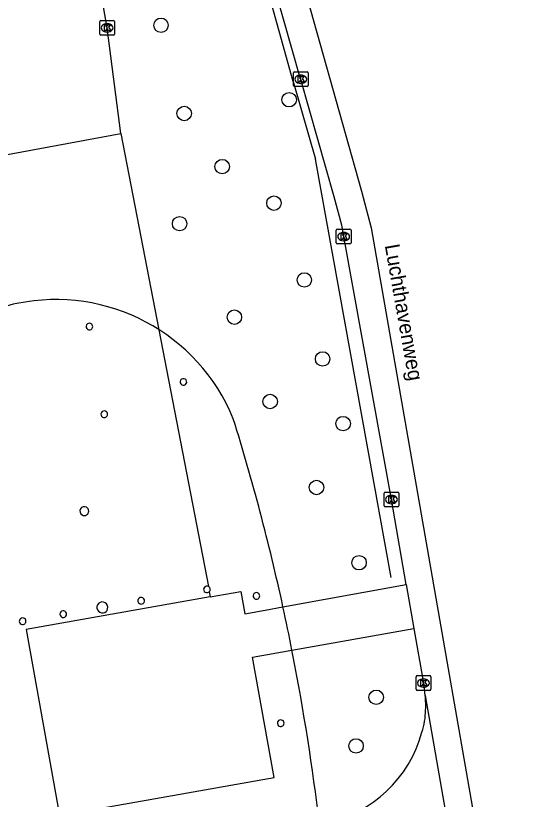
# Model space of a CAD drawing. Extents: x 152881 to 155736, y 382924 to 386919.
# Drawn here: x 155377.3 to 155412.3, y 385358.1 to 385411.1 of the extents above; entities that cross this region are included whole.
import ezdxf

# ---------------------------------------------------------------- set-up
doc = ezdxf.new("R2010")
doc.units = 0
for name, color, linetype in [('IMGEO_Boom', 7, 'Continuous'), ('IMGEO_Hek', 7, 'Continuous'), ('IMGEO_Kolk', 7, 'Continuous'), ('IMGEO_Openbare_ruimte_label', 7, 'Continuous'), ('IMGEO_Pand', 7, 'Continuous'), ('IMGEO_Pand_overbouw', 7, 'Continuous'), ('IMGEO_Rijbaan_lokaal_gesloten', 7, 'Continuous'), ('IMGEO_Voetpad_open', 7, 'Continuous')]:
    doc.layers.add(name, color=color, linetype=linetype)

msp = doc.modelspace()

# ---------------------------------------------------------------- linework, layer by layer
at = {"layer": 'IMGEO_Boom'}
for centre in [(155387.178, 385410.464), (155395.846, 385405.423), (155388.747, 385404.497), (155391.319, 385400.896), (155394.817, 385398.427), (155388.438, 385397.038), (155396.875, 385393.231), (155392.142, 385390.711), (155398.109, 385387.882), (155394.56, 385385.001), (155399.498, 385383.509), (155397.698, 385379.188), (155400.578, 385374.096), (155401.736, 385364.991), (155400.373, 385361.698)]:
    msp.add_circle(centre, 0.489, dxfattribs=at)
at = {"layer": 'IMGEO_Hek'}
for points in [[(155396.115, 385406.669), (155391.617, 385422.907)], [(155396.115, 385406.669), (155397.634, 385401.404)], [(155402.753, 385373.089), (155397.634, 385401.404)]]:
    msp.add_lwpolyline(points, dxfattribs=at)
at = {"layer": 'IMGEO_Kolk'}
for p, q in [((155383.03, 385409.86), (155383.03, 385410.712)), ((155383.105, 385410.786), (155383.957, 385410.786)), ((155384.031, 385410.712), (155384.031, 385409.86)), ((155383.518, 385410.566), (155383.543, 385410.566)), ((155383.957, 385409.786), (155383.105, 385409.786)), ((155383.541, 385410.006), (155383.516, 385410.006)), ((155396.131, 385406.385), (155396.131, 385407.237)), ((155396.206, 385407.311), (155397.058, 385407.311)), ((155396.619, 385407.091), (155396.644, 385407.091)), ((155397.132, 385407.237), (155397.132, 385406.385)), ((155396.642, 385406.531), (155396.617, 385406.531)), ((155397.058, 385406.311), (155396.206, 385406.311)), ((155399.036, 385395.737), (155399.036, 385396.589)), ((155399.111, 385396.663), (155399.963, 385396.663)), ((155399.524, 385396.443), (155399.549, 385396.443)), ((155400.037, 385396.589), (155400.037, 385395.737)), ((155399.547, 385395.883), (155399.522, 385395.883)), ((155399.963, 385395.663), (155399.111, 385395.663)), ((155402.342, 385378.869), (155403.194, 385378.869)), ((155402.267, 385377.943), (155402.267, 385378.795)), ((155402.755, 385378.649), (155402.78, 385378.649)), ((155403.268, 385378.795), (155403.268, 385377.943)), ((155403.194, 385377.869), (155402.342, 385377.869)), ((155402.778, 385378.089), (155402.753, 385378.089)), ((155404.432, 385365.529), (155404.432, 385366.381)), ((155404.507, 385366.455), (155405.359, 385366.455)), ((155404.92, 385366.235), (155404.945, 385366.235)), ((155405.433, 385366.381), (155405.433, 385365.529)), ((155404.943, 385365.675), (155404.918, 385365.675)), ((155405.359, 385365.455), (155404.507, 385365.455))]:
    msp.add_line(p, q, dxfattribs=at)
for points in [[(155383.03, 385409.86), (155383.03, 385410.712)], [(155383.105, 385410.786), (155383.957, 385410.786)], [(155384.031, 385410.712), (155384.031, 385409.86)], [(155383.351, 385410.486), (155383.474, 385410.486), (155383.474, 385410.335), (155383.604, 385410.486), (155383.768, 385410.486), (155383.622, 385410.335), (155383.775, 385410.086), (155383.623, 385410.086), (155383.538, 385410.25), (155383.474, 385410.183), (155383.474, 385410.086), (155383.351, 385410.086), (155383.351, 385410.486)], [(155383.957, 385409.786), (155383.105, 385409.786)], [(155396.131, 385406.385), (155396.131, 385407.237)], [(155396.206, 385407.311), (155397.058, 385407.311)], [(155396.452, 385407.011), (155396.575, 385407.011), (155396.575, 385406.86), (155396.705, 385407.011), (155396.869, 385407.011), (155396.723, 385406.86), (155396.876, 385406.611), (155396.724, 385406.611), (155396.639, 385406.775), (155396.575, 385406.708), (155396.575, 385406.611), (155396.452, 385406.611), (155396.452, 385407.011)], [(155397.132, 385407.237), (155397.132, 385406.385)], [(155397.058, 385406.311), (155396.206, 385406.311)], [(155399.036, 385395.737), (155399.036, 385396.589)], [(155399.111, 385396.663), (155399.963, 385396.663)], [(155400.037, 385396.589), (155400.037, 385395.737)], [(155399.357, 385396.363), (155399.48, 385396.363), (155399.48, 385396.212), (155399.61, 385396.363), (155399.774, 385396.363), (155399.628, 385396.212), (155399.781, 385395.963), (155399.629, 385395.963), (155399.544, 385396.127), (155399.48, 385396.06), (155399.48, 385395.963), (155399.357, 385395.963), (155399.357, 385396.363)], [(155399.963, 385395.663), (155399.111, 385395.663)], [(155402.342, 385378.869), (155403.194, 385378.869)], [(155402.267, 385377.943), (155402.267, 385378.795)], [(155402.588, 385378.569), (155402.711, 385378.569), (155402.711, 385378.418), (155402.841, 385378.569), (155403.005, 385378.569), (155402.859, 385378.418), (155403.012, 385378.169), (155402.86, 385378.169), (155402.775, 385378.333), (155402.711, 385378.266), (155402.711, 385378.169), (155402.588, 385378.169), (155402.588, 385378.569)], [(155403.268, 385378.795), (155403.268, 385377.943)], [(155403.194, 385377.869), (155402.342, 385377.869)], [(155404.432, 385365.529), (155404.432, 385366.381)], [(155404.507, 385366.455), (155405.359, 385366.455)], [(155404.753, 385366.155), (155404.876, 385366.155), (155404.876, 385366.004), (155405.006, 385366.155), (155405.17, 385366.155), (155405.024, 385366.004), (155405.177, 385365.755), (155405.025, 385365.755), (155404.94, 385365.919), (155404.876, 385365.852), (155404.876, 385365.755), (155404.753, 385365.755), (155404.753, 385366.155)], [(155405.433, 385366.381), (155405.433, 385365.529)], [(155405.359, 385365.455), (155404.507, 385365.455)]]:
    msp.add_lwpolyline(points, dxfattribs=at)
for centre, start, end in [((155383.107, 385410.71), 91.552, 178.448), ((155383.107, 385410.71), 91.552, 178.448), ((155383.955, 385410.71), 1.552, 88.448), ((155383.955, 385410.71), 1.552, 88.448), ((155383.107, 385409.862), 181.552, 268.448), ((155383.107, 385409.862), 181.552, 268.448), ((155383.955, 385409.862), 271.552, 358.448), ((155383.955, 385409.862), 271.552, 358.448), ((155396.208, 385407.235), 91.552, 178.448), ((155396.208, 385407.235), 91.552, 178.448), ((155397.056, 385407.235), 1.552, 88.448), ((155397.056, 385407.235), 1.552, 88.448), ((155396.208, 385406.387), 181.552, 268.448), ((155396.208, 385406.387), 181.552, 268.448), ((155397.056, 385406.387), 271.552, 358.448), ((155397.056, 385406.387), 271.552, 358.448), ((155399.113, 385396.587), 91.552, 178.448), ((155399.113, 385396.587), 91.552, 178.448), ((155399.961, 385396.587), 1.552, 88.448), ((155399.961, 385396.587), 1.552, 88.448), ((155399.113, 385395.739), 181.552, 268.448), ((155399.113, 385395.739), 181.552, 268.448), ((155399.961, 385395.739), 271.552, 358.448), ((155399.961, 385395.739), 271.552, 358.448), ((155402.344, 385378.793), 91.552, 178.448), ((155402.344, 385378.793), 91.552, 178.448), ((155403.192, 385378.793), 1.552, 88.448), ((155403.192, 385378.793), 1.552, 88.448), ((155402.344, 385377.945), 181.552, 268.448), ((155402.344, 385377.945), 181.552, 268.448), ((155403.192, 385377.945), 271.552, 358.448), ((155403.192, 385377.945), 271.552, 358.448), ((155404.509, 385366.379), 91.552, 178.448), ((155404.509, 385366.379), 91.552, 178.448), ((155405.357, 385366.379), 1.552, 88.448), ((155405.357, 385366.379), 1.552, 88.448), ((155404.509, 385365.531), 181.552, 268.448), ((155404.509, 385365.531), 181.552, 268.448), ((155405.357, 385365.531), 271.552, 358.448), ((155405.357, 385365.531), 271.552, 358.448)]:
    msp.add_arc(centre, 0.0765, start, end, dxfattribs=at)
for centre, major_axis, ratio, start_param, end_param in [((155383.517, 385410.286), (-0.387, 0.002), 0.722429, 4.712389, 7.853982), ((155383.542, 385410.286), (-0.39, 0.002), 0.717154, 1.570796, 4.712389), ((155396.618, 385406.811), (-0.387, 0.002), 0.722429, 4.712389, 7.853982), ((155396.643, 385406.811), (-0.39, 0.002), 0.717154, 1.570796, 4.712389), ((155399.523, 385396.163), (-0.387, 0.002), 0.722429, 4.712389, 7.853982), ((155399.548, 385396.163), (-0.39, 0.002), 0.717154, 1.570796, 4.712389), ((155402.754, 385378.369), (-0.387, 0.002), 0.722429, 4.712389, 7.853982), ((155402.779, 385378.369), (-0.39, 0.002), 0.717154, 1.570796, 4.712389), ((155404.919, 385365.955), (-0.387, 0.002), 0.722429, 4.712389, 7.853982), ((155404.944, 385365.955), (-0.39, 0.002), 0.717154, 1.570796, 4.712389)]:
    msp.add_ellipse(centre, major_axis=major_axis, ratio=ratio, start_param=start_param, end_param=end_param, dxfattribs=at)
at = {"layer": 'IMGEO_Pand'}
for centre, radius, start, end in [((155382.336, 385390.073), 0.225, 60.273, 239.7637), ((155382.336, 385390.073), 0.225, 239.9083, 60.1285), ((155388.693, 385386.326), 0.225, 60.0184, 240.0184), ((155388.693, 385386.326), 0.225, 240.2022, 59.8345), ((155383.34, 385384.14), 0.225, 60.0184, 240.0184), ((155383.341, 385384.14), 0.225, 239.9083, 60.1285), ((155381.991, 385377.584), 0.3, 59.9706, 239.9706), ((155381.991, 385377.584), 0.3, 239.9117, 60.0295), ((155390.283, 385372.292), 0.225, 60.273, 239.7637), ((155390.283, 385372.295), 0.227, 240.2222, 314.8021), ((155390.282, 385372.292), 0.226, 315.3951, 60.0486), ((155393.633, 385371.848), 0.225, 59.9546, 239.9546), ((155393.634, 385371.847), 0.225, 239.7172, 60.1921), ((155385.836, 385371.523), 0.225, 60.0184, 240.0184), ((155385.836, 385371.523), 0.225, 240.2022, 59.8345), ((155383.212, 385371.068), 0.372, 344.1221, 278.8133), ((155383.21, 385371.07), 0.374, 279.0078, 343.9276), ((155380.565, 385370.615), 0.223, 339.8988, 298.2724), ((155380.568, 385370.612), 0.22, 297.881, 340.2902), ((155377.816, 385370.135), 0.225, 338.7879, 280.157), ((155377.814, 385370.138), 0.227, 280.5233, 338.4216), ((155395.278, 385363.236), 0.224, 322.9257, 258.9762), ((155395.277, 385363.238), 0.226, 259.2842, 322.6178)]:
    msp.add_arc(centre, radius, start, end, dxfattribs=at)
at = {"layer": 'IMGEO_Pand_overbouw'}
msp.add_lwpolyline([(155396.102, 385367.846), (155396.037, 385368.183)], dxfattribs=at)
for centre, radius, start, end in [((155380.108, 385378.864), 13.048, 101.9085, 118.6529), ((155380.061, 385378.93), 12.973, 22.2188, 101.7642), ((155249.451, 385339.374), 149.39, 12.26524, 17.31494), ((155249.34, 385339.337), 149.506, 11.12437, 12.2699), ((155245.987, 385338.487), 152.959, 6.73678, 11.06618)]:
    msp.add_arc(centre, radius, start, end, dxfattribs=at)
at = {"layer": 'IMGEO_Rijbaan_lokaal_gesloten'}
for points in [[(155384.37, 385478.191), (155393.654, 385425.116), (155394.079, 385423.161), (155394.702, 385420.725), (155400.747, 385399.241), (155401.402, 385396.757), (155412.299, 385334.372)], [(155384.464, 385403.14), (155383.531, 385410.286), (155380.179, 385429.457), (155379.419, 385433.64)], [(155403.77, 385372.626), (155402.768, 385378.369), (155399.537, 385396.163), (155399.402, 385396.933), (155398.891, 385398.847), (155396.637, 385406.784), (155396.602, 385406.906), (155392.692, 385420.676)], [(155375.906, 385401.56), (155384.464, 385403.14)], [(155403.77, 385372.626), (155404.289, 385369.65)], [(155404.289, 385369.65), (155404.933, 385365.955)], [(155405.059, 385365.1), (155408.866, 385343.244)]]:
    msp.add_lwpolyline(points, dxfattribs=at)
for centre, radius, start, end in [((155397.362, 385364.403), 7.728, 5.1779, 11.5886), ((155397.799, 385364.439), 7.29, 357.4893, 5.1996), ((155399.757, 385364.242), 5.327, 342.2916, 358.6846), ((155396.618, 385364.84), 8.508, 281.4534, 344.8865)]:
    msp.add_arc(centre, radius, start, end, dxfattribs=at)
at = {"layer": 'IMGEO_Voetpad_open'}
for points in [[(155384.464, 385403.14), (155390.395, 385372.488)], [(155390.512, 385371.775), (155392.58, 385372.139), (155392.844, 385370.64), (155394.233, 385370.892), (155395.431, 385371.11), (155403.77, 385372.626)], [(155390.443, 385372.134), (155390.512, 385371.775)], [(155390.512, 385371.775), (155378.057, 385369.585), (155380.306, 385357), (155394.843, 385359.558), (155393.377, 385367.711), (155396.037, 385368.183), (155404.289, 385369.65)]]:
    msp.add_lwpolyline(points, dxfattribs=at)

# ---------------------------------------------------------------- texts
at = {"layer": 'IMGEO_Openbare_ruimte_label'}
msp.add_text('Luchthavenweg', height=1, rotation=280.0179, dxfattribs=at).set_placement((155402.313, 385395.569))

doc.saveas('drawing.dxf')
